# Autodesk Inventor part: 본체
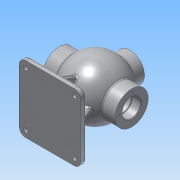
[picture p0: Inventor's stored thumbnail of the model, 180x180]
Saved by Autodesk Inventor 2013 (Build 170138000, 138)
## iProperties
Created: 2018-06
Part Number: 본체
Material: 알루미늄 6061
Document SubType Name: Modeling
Designer: Administrator
Density: 1 g/cm^3
Author: Administrator
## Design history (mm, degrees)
sketch "스케치1"
  geometry: L1 (-68, 0)-(68, 0); L2 (68, 17.5)-(68, 31); L3 (-68, 31)-(-68, 17.5); L4 (68, 31)-(42.988, 31); L5 (-42.988, 31)-(-68, 31); L6 (-68, 17.5)-(-39.278, 17.5); L7 (50.25, 0)-(52, 0); L8 (52, 17.5)-(52, 18.5); L9 (52, 18.5)-(50.25, 18.5); L10 (50.25, 18.5)-(50.25, 17.5); L11 (39.278, 17.5)-(50.25, 17.5); L12 (52, 17.5)-(68, 17.5); A1 r 53 centre (0, 0) between (42.988, 31) and (-42.988, 31); A2 r 43 centre (0, 0) between (39.278, 17.5) and (-39.278, 17.5); 2 further points
  constraints: 24 end point, 5 parallel, 5 perpendicular, 4 point on circle, 4 vertical alignment, 3 coincident, 3 collinear, 2 centre point, 2 horizontal, 1 midpoint, 1 point on line
  dimensions: "d0" = 106 diameter of A1; "d4" = 31 distance of L1.end L2.end; "d5" = 86 diameter of A2; "d6" = 17.5 distance of L2.start L1.end; "d8" = 136 distance between parallel lines of L2 L3; "d9" = 1.75 distance of L8.end L9.end; "d10" = 16 distance between parallel lines of L2 L8; "d11" = 18.5 distance between parallel lines of L7 L9
revolve "회전1" sketch "스케치1" stored, may be unused: angle "d12" = 90 deg
sketch "스케치2"
  geometry: L1 (-57.5, -85)-(57.5, -85); L2 (57.5, -85)-(57.5, -75); L3 (57.5, -75)-(-57.5, -75); L4 (-57.5, -75)-(-57.5, -85); L5 (-57.5, -85)-(57.5, -75); L6 (57.5, -85)-(-57.5, -75); 3 further points
  constraints: 12 end point, 3 midpoint, 2 parallel, 1 horizontal, 1 perpendicular, 1 vertical alignment
  dimensions: "d13" = 115 distance of L3.end L2.end; "d14" = 10 distance of L2.end L1.end; "d15" = 85 distance from line of L1 point (0, 0)
extrude "돌출1" join sketch "스케치2" stored distance "d16" = 125; taper "d17" = 0 deg
fillet "모깎기1" dims "d18" = 12
node "작업 평면1"
sketch "스케치3"
  geometry: C1 r 27 at (0, 0); 1 further point
  constraints: 1 centre point, 1 coincident
  dimensions: "d20" = 54 diameter of C1
extrude "돌출2" join sketch "스케치3" stored distance "d21" = 115; taper "d22" = 0 deg
sketch "스케치5"
  geometry: 2 further points
  dimensions: "d25" = 45.5 horizontal distance of point (0, 113) point (45.5, 62.5); "d26" = 50.5 vertical distance of point (0, 113) point (45.5, 62.5)
hole "구멍1" sketch "스케치5" at (0, 113) diameter "d27" = 8; stored, may be unused: countersink angle "d31" = 90 deg, drill point angle "d33" = 118 deg; dims "d28" = 6, "d29" = 12, "d30" = 3, "d32" = 8
sketch "스케치6"
  geometry: C1 r 31 at (0, 0) reference; 1 further point
  constraints: 1 vertical alignment
  dimensions: "d34" = 22.5 distance of C1.centre point (0, 22.5)
hole "구멍2" sketch "스케치6" at (0, 22.5) diameter "d35" = 3.242; stored, may be unused: countersink angle "d39" = 90 deg, drill point angle "d41" = 118 deg; dims "d36" = 12, "d37" = 12, "d38" = 3, "d40" = 15
sketch "스케치7"
  geometry: C1 r 17.5 at (0, 0) reference; 1 further point
  constraints: 1 vertical alignment
  dimensions: "d45" = 24 distance of C1.centre point (0, 24)
hole "구멍3" sketch "스케치7" at (0, 24) diameter "d46" = 3.242; stored, may be unused: countersink angle "d50" = 90 deg, drill point angle "d52" = 118 deg; dims "d47" = 16, "d48" = 12, "d49" = 3, "d51" = 19
sketch "스케치8"
  geometry: C1 r 27 at (0, 0) reference; C2 r 13 at (0, 0)
  constraints: 1 centre point, 1 coincident
  dimensions: "d56" = 26 diameter of C2
extrude "돌출3" cut sketch "스케치8" stored distance "d57" = 115; taper "d58" = 0 deg
sketch "스케치9"
  geometry: C1 r 13 at (0, 0) reference; 1 further point
  constraints: 1 vertical alignment
  dimensions: "d59" = 20 distance of C1.centre point (0, 20)
hole "구멍4" sketch "스케치9" at (0, 20) diameter "d60" = 3.242; stored, may be unused: countersink angle "d64" = 90 deg, drill point angle "d66" = 118 deg; dims "d61" = 9, "d62" = 12, "d63" = 3, "d65" = 11
sketch "스케치10"
  geometry: L1 (0, 125)-(91, 125) reference; L2 (41.5, 10)-(49.5, 10); L3 (49.5, 10)-(49.5, 115); L4 (49.5, 115)-(41.5, 115); L5 (41.5, 115)-(41.5, 10); L6 (41.5, 10)-(49.5, 115); L7 (49.5, 10)-(41.5, 115); 1 further point
  constraints: 12 end point, 2 midpoint, 2 parallel, 1 horizontal, 1 perpendicular
  dimensions: "d70" = 8 distance of L4.end L3.end; "d71" = 10 distance between parallel lines of L1 L4
extrude "돌출5" join sketch "스케치10" stored distance "d76" = 115; taper "d77" = 0 deg
feature "면 기울기1" dims angle "d78" = 22 deg
sketch "스케치11"
  geometry: L1 (47.5, -75)-(42.22, -61.931); L2 (57.5, -75)-(57.5, -85) reference; L3 (39.5, -75)-(51.5, -75) reference; 1 further point
  constraints: 2 end point, 1 point on line
  dimensions: "d79" = 22 deg angle of L2 L1; "d80" = 10 distance of L2.start L1.start
feature "리브1" sketch "스케치11" dims "d81" = 1, "d82" = 8, "d83" = 0, "d84" = 0, "d85" = 1, "d86" = 1
node "작업 평면2"
fillet "모깎기2" dims "d92" = 3
fillet "모깎기4" dims "d94" = 3
chamfer "모따기1" distance "d95" = 1; stored, may be unused: second distance "d96" = 2, angle "d97" = 45 deg
sketch "스케치13"
  geometry: L1 (-27, 65)-(27, 65) reference; L2 (-27, 65)-(-27, 47.286) reference; 2 further points
  constraints: 1 other
  dimensions: "d98" = 10 distance from line of L1 point (0, 55); "d99" = 27 distance from line of L2 point (0, 55)
feature "엠보싱2" sketch "스케치13" dims "d0" = 106, "d4" = 31, "d5" = 86, "d6" = 17.5, "d8" = 136, "d9" = 1.75, "d10" = 16, "d11" = 18.5, "d13" = 115, "d14" = 10, "d15" = 85, "d100" = 0.5, "d101" = 0
node "솔리드1"
mirror "대칭1"
mirror "대칭2"
pattern_circular "원형 패턴1" dims angle "d43" = 360 deg
pattern_circular "원형 패턴2" dims angle "d54" = 360 deg
pattern_circular "원형 패턴3" dims angle "d68" = 360 deg
mirror "대칭3"
other parameters: "d19" = 65, "d87" = -27
